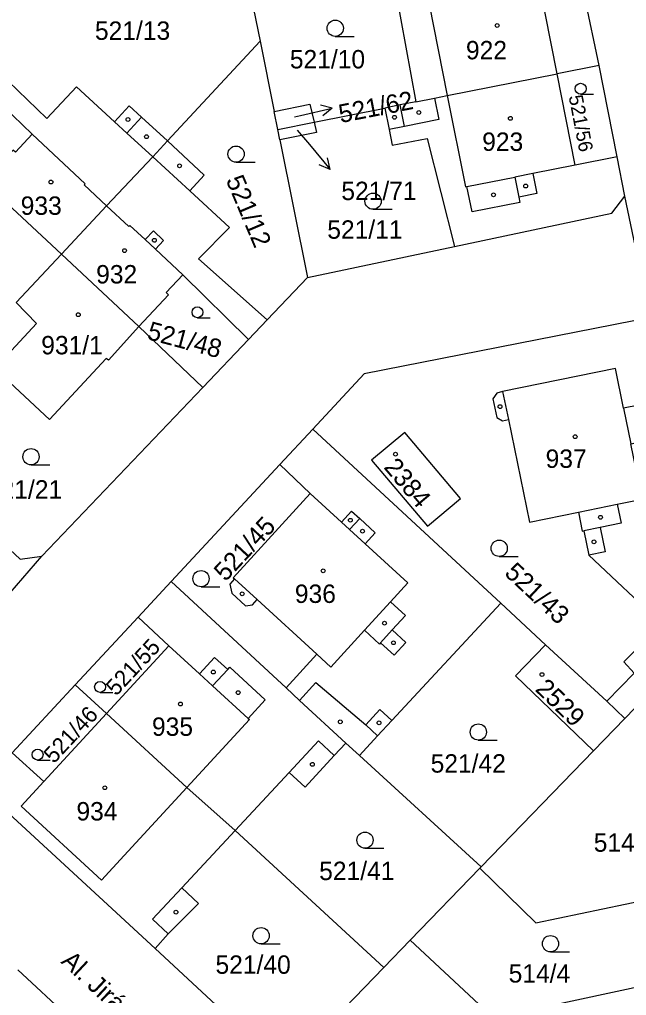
# Model space of a CAD drawing. Extents: x -679220 to -673243, y -1075091 to -1066557.
# Drawn here: x -675855 to -675798.9, y -1071743.1 to -1071652.9 of the extents above; entities that cross this region are included whole.
import ezdxf

# ---------------------------------------------------------------- set-up
doc = ezdxf.new("R2010")
doc.units = 0
for name, color, linetype in [('Hranice parcel', 7, 'Continuous'), ('Parcelní čísla', 7, 'Continuous'), ('Pop  PČ popisy', 7, 'Continuous'), ('Vnitřní kresba', 7, 'Continuous'), ('Značky budov', 7, 'Continuous'), ('Značky kultur', 7, 'Continuous')]:
    doc.layers.add(name, color=color, linetype=linetype)

msp = doc.modelspace()

# ---------------------------------------------------------------- linework, layer by layer
at = {"layer": 'Hranice parcel'}
for p, q in [((-675801.46, -1071657.17), (-675804.27, -1071643.7)), ((-675833.84, -1071649.66), (-675832.79, -1071654.92)), ((-675832.79, -1071654.92), (-675841.35, -1071664.14)), ((-675832.79, -1071654.92), (-675831.48, -1071661.41)), ((-675801.46, -1071657.17), (-675805.33, -1071657.94)), ((-675799.8, -1071665.61), (-675801.46, -1071657.17)), ((-675827.8, -1071662.4), (-675821.25, -1071661.1)), ((-675831.15, -1071663.07), (-675831.48, -1071661.41)), ((-675831.15, -1071663.07), (-675827.8, -1071662.4)), ((-675830.95, -1071664.05), (-675831.15, -1071663.07)), ((-675830.95, -1071664.05), (-675828.4, -1071676.75)), ((-675799.09, -1071669.23), (-675799.8, -1071665.61)), ((-675851.15, -1071674.6), (-675858.34, -1071667.91)), ((-675796.44, -1071681.97), (-675799.09, -1071669.23)), ((-675855.32, -1071679.07), (-675851.15, -1071674.6)), ((-675851.15, -1071674.6), (-675843.98, -1071681.28)), ((-675828.4, -1071676.75), (-675814.83, -1071673.89)), ((-675832.13, -1071680.67), (-675828.4, -1071676.75)), ((-675853.45, -1071681.02), (-675855.32, -1071679.07)), ((-675833.86, -1071682.48), (-675832.13, -1071680.67)), ((-675843.98, -1071681.28), (-675846.79, -1071684.4)), ((-675838.08, -1071686.91), (-675843.98, -1071681.28)), ((-675838.08, -1071686.91), (-675833.86, -1071682.48)), ((-675852.95, -1071702.5), (-675838.08, -1071686.91)), ((-675827.92, -1071690.76), (-675830.97, -1071694.04)), ((-675810.54, -1071706.86), (-675827.92, -1071690.76)), ((-675830.97, -1071694.04), (-675841, -1071704.86)), ((-675861.59, -1071712.49), (-675852.95, -1071702.5)), ((-675841, -1071704.86), (-675844.06, -1071708.16)), ((-675830.38, -1071714.66), (-675841, -1071704.86)), ((-675806.42, -1071710.69), (-675810.54, -1071706.86)), ((-675844.06, -1071708.16), (-675849.86, -1071714.41)), ((-675800.74, -1071715.91), (-675806.42, -1071710.69)), ((-675849.86, -1071714.41), (-675855.69, -1071720.69)), ((-675846.99, -1071717.06), (-675849.86, -1071714.41)), ((-675800.74, -1071715.91), (-675799.07, -1071717.5)), ((-675801.99, -1071720.5), (-675799.07, -1071717.5)), ((-675824.85, -1071719.78), (-675823.6, -1071720.93)), ((-675801.99, -1071720.5), (-675812.35, -1071731.21)), ((-675812.35, -1071731.21), (-675823.6, -1071720.93)), ((-675821.35, -1071740.52), (-675835.1, -1071727.86)), ((-675812.49, -1071731.35), (-675818.92, -1071738)), ((-675812.35, -1071731.21), (-675812.49, -1071731.35)), ((-675842.49, -1071738.77), (-675830.43, -1071749.89)), ((-675818.92, -1071738), (-675821.35, -1071740.52)), ((-675810.37, -1071745.94), (-675818.92, -1071738)), ((-675821.35, -1071740.52), (-675830.43, -1071749.89)), ((-675847.84, -1071747.53), (-675855.18, -1071740.72))]:
    msp.add_line(p, q, dxfattribs=at)
for points in [[(-675805.33, -1071657.94), (-675807.01, -1071649.5), (-675812.69, -1071650.63), (-675813.02, -1071648.97), (-675814.74, -1071649.31), (-675814.41, -1071650.97), (-675816.72, -1071651.43), (-675817.68, -1071646.43)], [(-675824.13, -1071647.74), (-675823.76, -1071649.58), (-675823.45, -1071651.08), (-675820.25, -1071650.4), (-675818.38, -1071660.53)], [(-675841.35, -1071664.14), (-675843.75, -1071661.94), (-675844.89, -1071660.89), (-675846.24, -1071662.37), (-675849.75, -1071659.14), (-675852.48, -1071662.07), (-675857.88, -1071656.89)], [(-675859.25, -1071658.34), (-675853.84, -1071663.53), (-675855.39, -1071665.19), (-675855.61, -1071664.98), (-675858.34, -1071667.91)], [(-675818.38, -1071660.53), (-675816.66, -1071660.18), (-675815.49, -1071659.95), (-675805.33, -1071657.94)], [(-675799.8, -1071665.61), (-675803.66, -1071666.37), (-675805.33, -1071657.94)], [(-675831.48, -1071661.41), (-675828.2, -1071660.75), (-675827.8, -1071662.4)], [(-675818.38, -1071660.53), (-675819.84, -1071660.82), (-675821.25, -1071661.1)], [(-675821.25, -1071661.1), (-675820.85, -1071663.09), (-675820.57, -1071664.53), (-675817.35, -1071663.92), (-675814.83, -1071673.89)], [(-675827.8, -1071662.4), (-675827.57, -1071663.37), (-675830.95, -1071664.05)], [(-675841.35, -1071664.14), (-675842.71, -1071665.61), (-675846.99, -1071670.13), (-675851.15, -1071674.6)], [(-675832.13, -1071680.67), (-675838.49, -1071675.05), (-675835.6, -1071672.14), (-675839.28, -1071668.76), (-675837.94, -1071667.3), (-675841.35, -1071664.14)], [(-675814.83, -1071673.89), (-675800.28, -1071670.82), (-675799.09, -1071669.23)], [(-675843.98, -1071681.28), (-675841.26, -1071678.36), (-675841.47, -1071678.15), (-675839.94, -1071676.5), (-675833.86, -1071682.48)], [(-675846.79, -1071684.4), (-675847, -1071684.24), (-675852.24, -1071689.88), (-675857.33, -1071685.18), (-675853.45, -1071681.02)], [(-675796.44, -1071681.97), (-675798.24, -1071680.76), (-675823.18, -1071685.65), (-675827.92, -1071690.76)], [(-675793.62, -1071696.4), (-675797.49, -1071697.24), (-675798.53, -1071692.12), (-675797.11, -1071691.83), (-675797.78, -1071688.55), (-675799.2, -1071688.84), (-675799.95, -1071685.16), (-675810.38, -1071687.29), (-675810.92, -1071687.45), (-675811.29, -1071687.97), (-675810.91, -1071689.69), (-675810.4, -1071690.01), (-675809.84, -1071689.89), (-675807.89, -1071699.36), (-675803.38, -1071698.44), (-675803.02, -1071700.21), (-675802.88, -1071700.18), (-675802.42, -1071702.43), (-675795.65, -1071708.76), (-675799.17, -1071712.26), (-675798.23, -1071713.32), (-675800.74, -1071715.91)], [(-675866.98, -1071691.57), (-675854.95, -1071702.78), (-675852.95, -1071702.5)], [(-675817.31, -1071699.75), (-675814.28, -1071697.18), (-675819.4, -1071691.08), (-675822.49, -1071693.64), (-675817.31, -1071699.75)], [(-675830.97, -1071694.04), (-675828.15, -1071696.73), (-675835.26, -1071704.51), (-675835.15, -1071704.61), (-675835.59, -1071705.09), (-675835.41, -1071705.92), (-675834.12, -1071707.1), (-675833.5, -1071707), (-675833.06, -1071706.52), (-675827.55, -1071711.55), (-675830.38, -1071714.66)], [(-675823.6, -1071720.93), (-675821.93, -1071719.1), (-675820.61, -1071717.7), (-675810.54, -1071706.86)], [(-675844.06, -1071708.16), (-675841.21, -1071710.78), (-675846.99, -1071717.06)], [(-675799.07, -1071717.5), (-675791.87, -1071710.05), (-675790.93, -1071709.09)], [(-675806.42, -1071710.69), (-675809.19, -1071713.58), (-675801.99, -1071720.5)], [(-675824.85, -1071719.78), (-675829.16, -1071715.85), (-675830.38, -1071714.66)], [(-675846.99, -1071717.06), (-675852.76, -1071723.33), (-675855.69, -1071720.69)], [(-675835.1, -1071727.86), (-675839.56, -1071723.89), (-675846.99, -1071717.06)], [(-675835.1, -1071727.86), (-675830.1, -1071722.49), (-675828.63, -1071723.85), (-675825.93, -1071720.94), (-675824.85, -1071719.78)], [(-675857.65, -1071722.81), (-675857.64, -1071724.8), (-675842.49, -1071738.77)], [(-675842.49, -1071738.77), (-675841.27, -1071737.42), (-675838.48, -1071734.59), (-675840.01, -1071733.14), (-675835.1, -1071727.86)], [(-675812.49, -1071731.35), (-675807.31, -1071736.39), (-675792.86, -1071733.38)], [(-675810.37, -1071745.94), (-675809.26, -1071744.74), (-675791.2, -1071740.86)]]:
    msp.add_lwpolyline(points, dxfattribs=at)
at = {"layer": 'Pop  PČ popisy'}
for p, q in [((-675829.04, -1071661.78), (-675826.116, -1071661.105)), ((-675826.116, -1071661.105), (-675827.204, -1071660.842)), ((-675826.116, -1071661.105), (-675826.979, -1071661.818)), ((-675829.6, -1071661.91), (-675829.04, -1071661.78)), ((-675829.37, -1071663.14), (-675828.23, -1071664.48)), ((-675828.23, -1071664.48), (-675826.301, -1071666.779)), ((-675826.301, -1071666.779), (-675826.561, -1071665.69)), ((-675826.301, -1071666.779), (-675827.328, -1071666.334))]:
    msp.add_line(p, q, dxfattribs=at)
at = {"layer": 'Vnitřní kresba'}
for p, q in [((-675817.16, -1071651.51), (-675815.49, -1071659.95)), ((-675816.66, -1071660.18), (-675816.26, -1071662.17)), ((-675815.49, -1071659.95), (-675813.81, -1071668.38)), ((-675819.44, -1071662.81), (-675819.84, -1071660.82)), ((-675845.1, -1071663.42), (-675843.75, -1071661.94)), ((-675846.24, -1071662.37), (-675845.1, -1071663.42)), ((-675819.44, -1071662.81), (-675820.85, -1071663.09)), ((-675816.26, -1071662.17), (-675819.44, -1071662.81)), ((-675848.95, -1071668.1), (-675853.84, -1071663.53)), ((-675845.1, -1071663.42), (-675842.71, -1071665.61)), ((-675842.71, -1071665.61), (-675839.28, -1071668.76)), ((-675803.66, -1071666.37), (-675807.58, -1071667.15)), ((-675813.67, -1071668.36), (-675809.25, -1071667.48)), ((-675807.58, -1071667.15), (-675809.25, -1071667.48)), ((-675809.25, -1071667.48), (-675808.88, -1071669.34)), ((-675807.58, -1071667.15), (-675807.21, -1071669.01)), ((-675849.05, -1071668.21), (-675848.95, -1071668.1)), ((-675846.99, -1071670.13), (-675849.05, -1071668.21)), ((-675813.81, -1071668.38), (-675813.67, -1071668.36)), ((-675813.2, -1071670.69), (-675813.67, -1071668.36)), ((-675807.21, -1071669.01), (-675808.88, -1071669.34)), ((-675808.88, -1071669.34), (-675808.79, -1071669.82)), ((-675846.99, -1071670.13), (-675844.92, -1071672.06)), ((-675808.79, -1071669.82), (-675813.2, -1071670.69)), ((-675844.92, -1071672.06), (-675844.82, -1071671.95)), ((-675844.82, -1071671.95), (-675843.41, -1071673.26)), ((-675843.41, -1071673.26), (-675842.65, -1071672.45)), ((-675842.65, -1071672.45), (-675841.7, -1071673.34)), ((-675843.41, -1071673.26), (-675842.46, -1071674.15)), ((-675841.7, -1071673.34), (-675842.46, -1071674.15)), ((-675842.46, -1071674.15), (-675839.94, -1071676.5)), ((-675810.38, -1071687.29), (-675809.84, -1071689.89)), ((-675799.2, -1071688.84), (-675798.53, -1071692.12)), ((-675828.15, -1071696.73), (-675825.27, -1071699.37)), ((-675799.78, -1071697.71), (-675797.49, -1071697.24)), ((-675803.38, -1071698.44), (-675799.78, -1071697.71)), ((-675799.78, -1071697.71), (-675799.42, -1071699.47)), ((-675825.27, -1071699.37), (-675824.33, -1071698.35)), ((-675823.57, -1071699.04), (-675824.51, -1071700.06)), ((-675824.33, -1071698.35), (-675823.57, -1071699.04)), ((-675823.57, -1071699.04), (-675822.15, -1071700.34)), ((-675825.27, -1071699.37), (-675824.51, -1071700.06)), ((-675801.36, -1071699.87), (-675802.88, -1071700.18)), ((-675799.42, -1071699.47), (-675801.36, -1071699.87)), ((-675801.36, -1071699.87), (-675800.9, -1071702.12)), ((-675824.51, -1071700.06), (-675823.08, -1071701.37)), ((-675822.15, -1071700.34), (-675823.08, -1071701.37)), ((-675823.08, -1071701.37), (-675819.13, -1071704.98)), ((-675800.9, -1071702.12), (-675802.42, -1071702.43)), ((-675835.15, -1071704.61), (-675833.06, -1071706.52)), ((-675820.73, -1071706.73), (-675819.13, -1071704.98)), ((-675823.13, -1071709.36), (-675820.73, -1071706.73)), ((-675820.73, -1071706.73), (-675819.35, -1071707.99)), ((-675819.35, -1071707.99), (-675820.57, -1071709.33)), ((-675826.24, -1071712.76), (-675823.13, -1071709.36)), ((-675821.75, -1071710.63), (-675823.13, -1071709.36)), ((-675820.57, -1071709.33), (-675821.65, -1071710.52)), ((-675820.57, -1071709.33), (-675819.31, -1071710.48)), ((-675841.21, -1071710.78), (-675838.38, -1071713.38)), ((-675821.65, -1071710.52), (-675821.75, -1071710.63)), ((-675820.39, -1071711.66), (-675821.65, -1071710.52)), ((-675819.31, -1071710.48), (-675820.39, -1071711.66)), ((-675827.55, -1071711.55), (-675826.24, -1071712.76)), ((-675838.38, -1071713.38), (-675837, -1071711.87)), ((-675837, -1071711.87), (-675835.78, -1071712.99)), ((-675838.38, -1071713.38), (-675837.17, -1071714.5)), ((-675835.78, -1071712.99), (-675837.17, -1071714.5)), ((-675835.78, -1071712.99), (-675835.58, -1071712.77)), ((-675835.58, -1071712.77), (-675832.31, -1071715.77)), ((-675829.16, -1071715.85), (-675827.63, -1071714.17)), ((-675827.63, -1071714.17), (-675823.01, -1071718.09)), ((-675837.17, -1071714.5), (-675833.89, -1071717.5)), ((-675832.31, -1071715.77), (-675833.89, -1071717.5)), ((-675823.01, -1071718.09), (-675821.71, -1071716.68)), ((-675821.71, -1071716.68), (-675820.61, -1071717.7)), ((-675833.78, -1071717.6), (-675839.56, -1071723.89)), ((-675833.89, -1071717.5), (-675833.78, -1071717.6)), ((-675823.01, -1071718.09), (-675821.93, -1071719.1)), ((-675830.1, -1071722.49), (-675827.38, -1071719.56)), ((-675827.38, -1071719.56), (-675825.93, -1071720.94)), ((-675854.85, -1071725.6), (-675852.76, -1071723.33)), ((-675839.56, -1071723.89), (-675845.34, -1071730.18)), ((-675847.43, -1071732.46), (-675854.85, -1071725.6)), ((-675845.34, -1071730.18), (-675847.43, -1071732.46)), ((-675842.73, -1071736.06), (-675840.01, -1071733.14)), ((-675841.27, -1071737.42), (-675842.73, -1071736.06))]:
    msp.add_line(p, q, dxfattribs=at)
at = {"layer": 'Značky budov'}
for centre in [(-675810.877, -1071653.479), (-675844.997, -1071662.159), (-675820.367, -1071661.959), (-675818.117, -1071661.509), (-675809.657, -1071662.059), (-675843.277, -1071663.749), (-675840.227, -1071666.439), (-675852.107, -1071667.939), (-675808.247, -1071668.309), (-675811.217, -1071669.119), (-675842.557, -1071673.319), (-675845.307, -1071674.279), (-675849.587, -1071680.199), (-675810.617, -1071688.689), (-675803.677, -1071691.469), (-675820.277, -1071693.089), (-675824.447, -1071699.189), (-675801.337, -1071698.919), (-675823.327, -1071700.199), (-675801.937, -1071701.179), (-675826.957, -1071703.869), (-675834.437, -1071705.989), (-675821.287, -1071708.699), (-675820.467, -1071710.509), (-675837.107, -1071713.219), (-675806.737, -1071713.449), (-675834.817, -1071715.119), (-675840.147, -1071716.169), (-675825.377, -1071717.819), (-675821.797, -1071717.909), (-675827.957, -1071721.749), (-675847.127, -1071723.909), (-675840.557, -1071735.409)]:
    msp.add_circle(centre, 0.175, dxfattribs=at)
at = {"layer": 'Značky kultur'}
for p, q in [((-675825.843, -1071654.48), (-675824.093, -1071654.48)), ((-675803.165, -1071659.82), (-675801.993, -1071659.82)), ((-675835.003, -1071666.11), (-675833.253, -1071666.11)), ((-675822.343, -1071670.46), (-675820.593, -1071670.46)), ((-675838.575, -1071680.48), (-675837.403, -1071680.48)), ((-675853.953, -1071694.07), (-675852.203, -1071694.07)), ((-675810.693, -1071702.53), (-675808.943, -1071702.53)), ((-675838.243, -1071705.34), (-675836.493, -1071705.34)), ((-675847.575, -1071715.1), (-675846.403, -1071715.1)), ((-675812.623, -1071719.51), (-675810.873, -1071719.51)), ((-675853.345, -1071721.35), (-675852.173, -1071721.35)), ((-675823.093, -1071729.5), (-675821.343, -1071729.5)), ((-675832.693, -1071738.33), (-675830.943, -1071738.33)), ((-675805.953, -1071739.07), (-675804.203, -1071739.07))]:
    msp.add_line(p, q, dxfattribs=at)
for centre, radius in [((-675825.843, -1071653.73), 0.75), ((-675803.165, -1071659.317), 0.502), ((-675835.003, -1071665.36), 0.75), ((-675822.343, -1071669.71), 0.75), ((-675838.575, -1071679.977), 0.502), ((-675853.953, -1071693.32), 0.75), ((-675810.693, -1071701.78), 0.75), ((-675838.243, -1071704.59), 0.75), ((-675847.575, -1071714.597), 0.502), ((-675812.623, -1071718.76), 0.75), ((-675853.345, -1071720.847), 0.502), ((-675823.093, -1071728.75), 0.75), ((-675832.693, -1071737.58), 0.75), ((-675805.953, -1071738.32), 0.75)]:
    msp.add_circle(centre, radius, dxfattribs=at)

# ---------------------------------------------------------------- texts
at = {"layer": 'Parcelní čísla'}
for s, p in [('521/13', (-675848.047, -1071654.8)), ('922', (-675813.765, -1071656.6)), ('521/10', (-675830.037, -1071657.44)), ('923', (-675812.265, -1071665.06)), ('521/71', (-675825.28, -1071669.608)), ('933', (-675854.905, -1071670.97)), ('521/11', (-675826.577, -1071673.18)), ('932', (-675847.935, -1071677.31)), ('931/1', (-675853.008, -1071683.86)), ('937', (-675806.405, -1071694.35)), ('521/21', (-675858.027, -1071697.19)), ('936', (-675829.575, -1071706.83)), ('935', (-675842.775, -1071719.11)), ('521/42', (-675817.027, -1071722.509)), ('934', (-675849.755, -1071726.93)), ('514/3', (-675801.958, -1071729.82)), ('521/41', (-675827.327, -1071732.44)), ('521/40', (-675836.907, -1071741.1)), ('514/4', (-675809.818, -1071741.91))]:
    msp.add_text(s, height=1.7, dxfattribs=at).set_placement(p)
for s, height, rotation, p in [('521/62', 1.7, 11, (-675825.347, -1071662.494)), ('521/56', 1.3, 281, (-675804.284, -1071660.02)), ('521/12', 1.7, 293, (-675835.974, -1071667.748)), ('521/48', 1.7, 345, (-675843.323, -1071682.429)), ('2384', 1.7, 310, (-675821.422, -1071694.327)), ('521/45', 1.7, 47, (-675835.98, -1071704.926)), ('521/43', 1.7, 317, (-675810.296, -1071704.179)), ('521/55', 1.5, 47, (-675846.087, -1071715.498)), ('2529', 1.7, 316, (-675807.449, -1071714.885)), ('521/46', 1.5, 47, (-675851.837, -1071721.738))]:
    msp.add_text(s, height=height, rotation=rotation, dxfattribs=at).set_placement(p)
at = {"layer": 'Pop  PČ popisy'}
msp.add_text('Al. Jiráska', height=1.7, rotation=317, dxfattribs=at).set_placement((-675851.264, -1071740.052))

doc.saveas('drawing.dxf')
